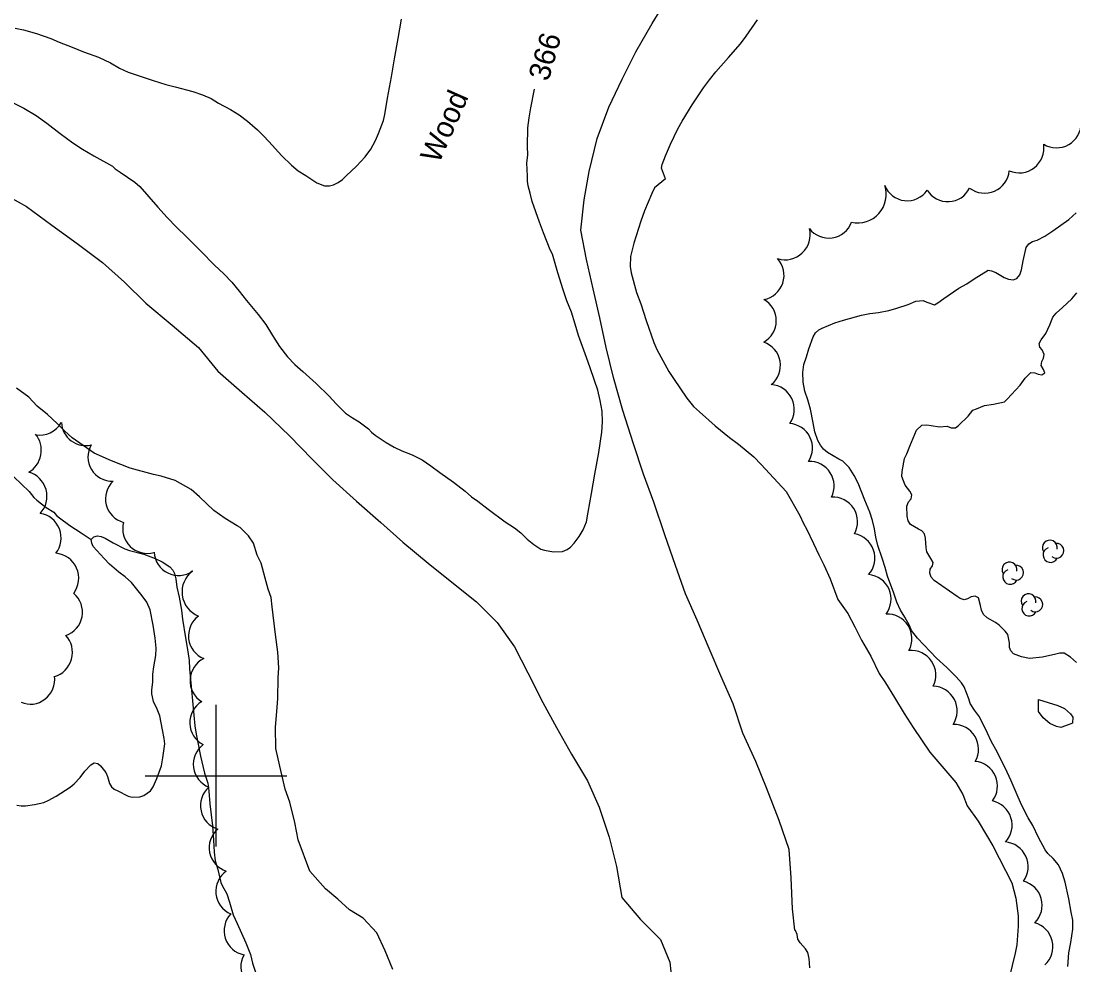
# Model space of a CAD drawing. Extents: x 287698 to 290158, y 5234163 to 5237182.
# Drawn here: x 288572.5 to 288721, y 5235573.3 to 5235706.5 of the extents above; entities that cross this region are included whole.
import ezdxf

# ---------------------------------------------------------------- set-up
doc = ezdxf.new("R2010")
doc.units = 0
for name, color, linetype in [('Niveau 2', 7, 'Continuous'), ('Niveau 4', 7, 'Continuous'), ('Niveau 44', 7, 'Continuous'), ('Niveau 61', 7, 'Continuous')]:
    doc.layers.add(name, color=color, linetype=linetype)

msp = doc.modelspace()

# ---------------------------------------------------------------- linework, layer by layer
at = {"layer": 'Niveau 2'}
for points in [[(288681.74, 5235578.21), (288681.41, 5235581.23), (288681.26, 5235585.59), (288680.94, 5235589.59), (288679.52, 5235593.66), (288677.73, 5235598.29), (288676.23, 5235602.03), (288674.42, 5235606.03), (288673.04, 5235610.13), (288671.32, 5235614.08), (288669.65, 5235617.95), (288667.95, 5235621.96), (288666.29, 5235625.7), (288664.88, 5235629.68), (288663.41, 5235634.01), (288661.82, 5235638.6), (288660.4, 5235642.55), (288658.95, 5235646.83), (288657.48, 5235651.54), (288656.13, 5235656.23), (288655.1, 5235660.45), (288654.22, 5235664.63), (288653.28, 5235668.75), (288652.31, 5235672.87), (288651.52, 5235677.02), (288652.02, 5235681.3), (288652.73, 5235685.31), (288653.85, 5235689.96), (288655.49, 5235694.37), (288657.38, 5235698.34), (288659.29, 5235702.19), (288661.62, 5235706.17), (288663.73, 5235709.65)], [(288571.63, 5235705.55), (288572.82, 5235705.29), (288574.67, 5235704.76), (288576.66, 5235704.06), (288577.84, 5235703.55), (288579.7, 5235702.86), (288581.31, 5235702.21), (288583.39, 5235701.44), (288585.12, 5235700.62), (288586.36, 5235699.9), (288587.62, 5235699.31), (288588.71, 5235698.95), (288591.11, 5235698.13), (288592.94, 5235697.56), (288594.23, 5235697.26), (288596.75, 5235696.61), (288598.09, 5235696.12), (288599.32, 5235695.58), (288600.37, 5235694.96), (288602.04, 5235694.05), (288603.26, 5235693.29), (288604.45, 5235692.39), (288605.86, 5235691.18), (288606.71, 5235690.35), (288607.46, 5235689.51), (288609.32, 5235687.53), (288610.69, 5235686.17), (288611.63, 5235685.41), (288612.71, 5235684.72), (288614.23, 5235683.68), (288615.33, 5235683.26), (288616.04, 5235683.26), (288616.6, 5235683.42), (288617.27, 5235683.73), (288617.88, 5235684.17), (288618.41, 5235684.69), (288619.86, 5235686.03), (288621.09, 5235687.36), (288621.87, 5235688.43), (288622.54, 5235689.66), (288622.97, 5235690.67), (288623.67, 5235692.5), (288623.84, 5235693.35), (288624.24, 5235695.64), (288624.77, 5235698.66), (288625.22, 5235701.2), (288625.72, 5235704.05), (288626.21, 5235706.82)], [(288663.51, 5235684.28), (288662.93, 5235685.78), (288663.04, 5235686.28), (288663.47, 5235687.49), (288664.19, 5235689.14), (288665.22, 5235691.3), (288665.84, 5235692.39), (288667.25, 5235694.72), (288668.84, 5235697.09), (288669.71, 5235698.25), (288670.62, 5235699.37), (288672.37, 5235701.37), (288674.07, 5235703.32), (288674.87, 5235704.39), (288676.5, 5235706.71)], [(288649.56, 5235667.05), (288649.03, 5235668.61), (288648.27, 5235670.98), (288647.51, 5235673.62), (288647.22, 5235674.25), (288646.24, 5235676.66), (288645.69, 5235678.16), (288644.65, 5235681.08), (288644.36, 5235682.24), (288644.08, 5235683.29), (288643.99, 5235683.91), (288644.01, 5235684.65), (288643.91, 5235686.51), (288644.03, 5235687.61), (288644.01, 5235688.89), (288644.04, 5235691.46), (288644.23, 5235692.88), (288644.48, 5235694.29), (288644.99, 5235696.92)], [(288570.05, 5235695.63), (288572.85, 5235694.25), (288574.63, 5235693.18), (288576.11, 5235692.1), (288578, 5235690.65), (288579.77, 5235689.34), (288581.16, 5235688.43), (288582.73, 5235687.52), (288585.37, 5235686.03), (288585.76, 5235685.66), (288586.47, 5235685.2), (288588.56, 5235683.79), (288589.26, 5235683.16), (288590.53, 5235681.74), (288591.78, 5235680.24), (288593.09, 5235678.8), (288594.41, 5235677.46), (288595.84, 5235676.09), (288597.85, 5235674.04), (288599.81, 5235672.05), (288601.09, 5235670.85), (288602.23, 5235669.69), (288603.3, 5235668.41), (288604.33, 5235667.09), (288605.96, 5235665.13), (288607.03, 5235663.69), (288607.99, 5235662.14), (288608.99, 5235660.61), (288610.08, 5235659.15), (288611.15, 5235658.04), (288612.28, 5235657.04), (288614.17, 5235655.35), (288616.01, 5235653.57), (288616.98, 5235652.52), (288618.29, 5235651.2), (288619.26, 5235650.53), (288620.23, 5235649.96), (288621.56, 5235648.96), (288621.96, 5235648.48), (288622.48, 5235648.09), (288624.02, 5235647.04), (288625.18, 5235646.37), (288626.24, 5235645.85), (288627.72, 5235645.28), (288629.11, 5235644.59), (288630.36, 5235643.73), (288631.63, 5235642.79), (288633.55, 5235641.46), (288635.2, 5235640.17), (288636.11, 5235639.37), (288637, 5235638.74), (288638.45, 5235637.61), (288640.85, 5235635.82), (288642.18, 5235634.99), (288643.05, 5235634.3), (288643.95, 5235633.4), (288644.9, 5235632.63), (288645.87, 5235631.98), (288646.42, 5235631.83), (288647.69, 5235631.6), (288648.93, 5235631.66), (288649.6, 5235631.95), (288650.05, 5235632.27), (288650.61, 5235632.83), (288651.29, 5235633.76), (288651.88, 5235634.69), (288652.31, 5235635.82), (288652.57, 5235637.2), (288653.04, 5235639.84), (288653.52, 5235642.58), (288654.06, 5235645.61), (288654.52, 5235648.51), (288654.61, 5235649.97), (288654.53, 5235651.48), (288654.28, 5235652.95), (288653.92, 5235654.43), (288653.48, 5235655.81), (288652.82, 5235657.74), (288652.13, 5235659.54), (288651.18, 5235662.16), (288650.74, 5235663.75), (288650.2, 5235665.44), (288649.56, 5235667.05)], [(288663.51, 5235684.28), (288661.93, 5235683), (288661.55, 5235682.2), (288660.5, 5235679.72), (288660.01, 5235678.29), (288659, 5235675.16), (288658.55, 5235673.3), (288658.49, 5235671.88), (288658.66, 5235670.98), (288659.37, 5235668.22), (288660.02, 5235666.61), (288660.78, 5235664.27), (288661.82, 5235661.14), (288662.28, 5235660.15), (288663.96, 5235657.04), (288664.62, 5235656.08), (288666.49, 5235653.32), (288667.42, 5235652.11), (288668.28, 5235651.35), (288670.49, 5235649.41), (288672.54, 5235647.73), (288673.82, 5235646.8), (288675.98, 5235645.04), (288677.01, 5235643.92), (288680.52, 5235640.11), (288682.48, 5235636.73), (288682.98, 5235635.6), (288683.38, 5235634.84), (288684.37, 5235632.77), (288685.16, 5235631.17), (288685.85, 5235629.76), (288686.75, 5235627.78), (288687.85, 5235624.86), (288689.22, 5235622.88), (288690.21, 5235621), (288691.19, 5235619.12), (288692.48, 5235616.86), (288693.66, 5235614.42), (288694.54, 5235613.1), (288695.82, 5235611.04), (288697.19, 5235608.78), (288698.47, 5235606.82), (288700.82, 5235603.34), (288704.51, 5235599.04), (288705.5, 5235597.35), (288706.1, 5235595.74), (288707.66, 5235593.59), (288708.84, 5235591.61), (288709.73, 5235590.11), (288712.39, 5235584.87), (288712.97, 5235582.73), (288713.3, 5235580.21), (288713.32, 5235578.75), (288713.09, 5235576.11), (288712.88, 5235574.95), (288712.04, 5235571.48)], [(288569.7, 5235682.35), (288573.22, 5235680.35), (288576.84, 5235677.7), (288580.4, 5235675.15), (288583.99, 5235672.46), (288587.06, 5235669.65), (288590.1, 5235666.73), (288593.81, 5235663.62), (288597.54, 5235660.46), (288600.27, 5235657.1), (288603.64, 5235654.13), (288606.9, 5235651.31), (288610.4, 5235647.96), (288613.58, 5235644.67), (288616.52, 5235641.75), (288619.86, 5235638.75), (288623.3, 5235635.75), (288626.39, 5235632.95), (288629.95, 5235630), (288633.29, 5235627.34), (288636.81, 5235624.56), (288639.72, 5235621.64), (288642.17, 5235618.19), (288644.03, 5235614.51), (288646.18, 5235610.33), (288648.09, 5235606.8), (288650.2, 5235603.06), (288652.49, 5235599.3), (288654.11, 5235595.58), (288655.54, 5235591.32), (288656.58, 5235587.21), (288657.34, 5235582.82), (288659.98, 5235579.72), (288662.79, 5235576.86), (288664.09, 5235573.67)], [(288603.01, 5235635.29), (288601.29, 5235636.31), (288599.69, 5235637.46), (288597.69, 5235639.38), (288596.49, 5235640.41), (288594.23, 5235641.67), (288592.26, 5235642.28), (288591.2, 5235642.52), (288587.89, 5235643.4), (288585.25, 5235644.46), (288582.81, 5235645.52), (288579.7, 5235647.68), (288578.63, 5235648.7), (288577.57, 5235649.72), (288576.23, 5235651.01), (288574.76, 5235652.16), (288573.56, 5235653.45), (288571.83, 5235654.73)], [(288624.99, 5235572.63), (288623.88, 5235575.3), (288622.7, 5235577.83), (288620.78, 5235579.88), (288618.85, 5235581.07), (288617.2, 5235582.56), (288615.47, 5235584.04), (288613.24, 5235586.54), (288611.59, 5235590.94), (288611.15, 5235593.42), (288610.45, 5235596.29), (288609.75, 5235598.11), (288609.04, 5235601.37), (288608.46, 5235603.85), (288608.41, 5235606.86), (288608.62, 5235609.08), (288608.72, 5235610.92), (288608.8, 5235613.81), (288608.9, 5235615.25), (288608.73, 5235617.46), (288608.41, 5235619.95), (288607.95, 5235623.86), (288607.79, 5235625.17), (288607.38, 5235626.34), (288606.95, 5235627.9), (288606.39, 5235629.99), (288605.84, 5235631.15), (288605.28, 5235632.85), (288604.61, 5235633.88), (288603.41, 5235635.04), (288603.01, 5235635.29)], [(288683.88, 5235572.9), (288683.8, 5235574.18), (288683.6, 5235575.05), (288683.28, 5235575.58), (288682.51, 5235576.42), (288682.19, 5235576.92), (288682.07, 5235577.6), (288681.86, 5235578.15), (288681.74, 5235578.21)], [(288664.09, 5235573.67), (288664.39, 5235571.06)]]:
    msp.add_lwpolyline(points, dxfattribs=at)
at = {"layer": 'Niveau 4'}
for points in [[(288719.01, 5235587.42), (288718.25, 5235588.32), (288717.47, 5235589), (288717.12, 5235589.52), (288716.19, 5235591.3), (288715.39, 5235592.98), (288714.72, 5235594.08), (288713.82, 5235595.82), (288713.3, 5235596.98), (288712.33, 5235599.3), (288711.76, 5235600.5), (288710.39, 5235603.26), (288709.48, 5235604.89), (288708.95, 5235606.02), (288707.84, 5235608.3), (288707.12, 5235609.25), (288706.54, 5235610.21), (288706.34, 5235610.85), (288705.69, 5235612.54), (288705.3, 5235613.13), (288704.53, 5235613.95), (288703.22, 5235615.27), (288701.77, 5235616.58), (288700.86, 5235617.54), (288699.09, 5235619.44), (288698.25, 5235620.52), (288697.94, 5235621.19), (288697.31, 5235622.38), (288696.67, 5235623.37), (288696.17, 5235624.51), (288695.72, 5235625.75), (288694.85, 5235628.19), (288694.53, 5235629.4), (288694.07, 5235630.7), (288693.49, 5235632.51), (288693.19, 5235633.7), (288693.02, 5235634.87), (288692.74, 5235636.04), (288692.34, 5235637.19), (288691.66, 5235638.91), (288690.71, 5235641.29), (288690.13, 5235642.37), (288689.45, 5235643.5), (288688.53, 5235644.41), (288687.95, 5235644.71), (288686.35, 5235645.63), (288685.82, 5235646.09), (288685.4, 5235646.65), (288685.02, 5235647.34), (288684.6, 5235648.55), (288684.33, 5235649.81), (288683.98, 5235651.73), (288683.61, 5235653.06), (288683.15, 5235654.31), (288682.94, 5235655.54), (288682.9, 5235656.91), (288683.01, 5235658.03), (288683.4, 5235659.11), (288683.74, 5235660.25), (288684.33, 5235661.96), (288684.67, 5235662.5), (288685.16, 5235662.93), (288685.62, 5235663.17), (288687.41, 5235663.93), (288688.65, 5235664.32), (288691.16, 5235665.02), (288692.34, 5235665.24), (288693.59, 5235665.4), (288695.02, 5235665.68), (288696.18, 5235665.98), (288697.78, 5235666.51), (288698.86, 5235666.99), (288699.9, 5235667.08), (288700.41, 5235666.86), (288701.48, 5235666.48), (288701.94, 5235666.75), (288702.81, 5235667.37), (288704.92, 5235668.83), (288706.06, 5235669.45), (288707.06, 5235670.15), (288709.05, 5235671.36), (288709.55, 5235671.27), (288710.13, 5235671.04), (288711.3, 5235670.35), (288711.94, 5235670.11), (288712.58, 5235670.01), (288713.12, 5235670.2), (288713.55, 5235670.73), (288713.78, 5235671.43), (288714, 5235672.69), (288714.41, 5235674.58), (288714.8, 5235675.08), (288715.32, 5235675.42), (288715.97, 5235675.59), (288717.08, 5235676.16), (288718.19, 5235676.91), (288720.45, 5235678.53), (288721.5, 5235679.48)], [(288711.84, 5235619.96), (288711.44, 5235620.42), (288710.63, 5235621.24), (288710.09, 5235621.61), (288708.92, 5235622.29), (288708.4, 5235622.78), (288708.1, 5235623.38), (288707.99, 5235624.01), (288707.71, 5235625.1), (288707.23, 5235625.33), (288706.64, 5235625.26), (288706.16, 5235624.96), (288705.67, 5235624.84), (288705.11, 5235625.03), (288704.68, 5235625.29), (288703.59, 5235626.06), (288701.42, 5235627.56), (288701.01, 5235628.02), (288700.82, 5235628.59), (288700.87, 5235629.18), (288701.18, 5235629.62), (288701.3, 5235630.12), (288700.95, 5235630.65), (288700.41, 5235631.63), (288700.3, 5235632.18), (288700.23, 5235633.52), (288700.06, 5235634.16), (288699.71, 5235634.55), (288699.2, 5235634.8), (288698.09, 5235635.45), (288697.78, 5235635.99), (288697.63, 5235636.63), (288697.57, 5235638.03), (288697.82, 5235638.65), (288698.2, 5235639.09), (288698.28, 5235639.63), (288698, 5235640.18), (288697.35, 5235641.03), (288696.87, 5235642.23), (288696.93, 5235642.95), (288697.25, 5235644.77), (288697.56, 5235645.42), (288697.99, 5235646.52), (288698.93, 5235648.78), (288699.7, 5235649.5), (288700.39, 5235649.54), (288700.99, 5235649.42), (288702.17, 5235649.27), (288703.29, 5235649.33), (288703.85, 5235649.11), (288704.46, 5235649.09), (288704.89, 5235649.46), (288706.22, 5235650.78), (288706.9, 5235651.61), (288707.4, 5235651.79), (288708.56, 5235652.28), (288709.8, 5235652.44), (288711.36, 5235652.78), (288711.75, 5235653.18), (288713.57, 5235655.15), (288714.29, 5235656.13), (288715.09, 5235656.9), (288715.64, 5235656.86), (288716.12, 5235656.67), (288716.65, 5235656.57), (288717.08, 5235656.87), (288716.89, 5235657.36), (288716.54, 5235657.9), (288716.63, 5235658.47), (288716.88, 5235658.95), (288716.96, 5235659.48), (288716.7, 5235660.1), (288716.35, 5235660.52), (288716.28, 5235661.03), (288716.54, 5235661.53), (288717.21, 5235662.43), (288717.75, 5235663.64), (288718.18, 5235664.73), (288718.67, 5235665.32), (288719.57, 5235666.11), (288720.88, 5235667.32), (288721.56, 5235668.19)], [(288571.44, 5235642.18), (288573.62, 5235640.14), (288574.29, 5235639.28), (288574.69, 5235638.89), (288576.01, 5235637.86), (288577.09, 5235637.21), (288577.47, 5235636.74), (288577.88, 5235636.4), (288579.36, 5235635.33), (288580.97, 5235634.31), (288582.37, 5235633.33)], [(288571.89, 5235595.85), (288572.5, 5235595.75), (288573.12, 5235595.77), (288574.35, 5235595.92), (288575.67, 5235596.23), (288576.3, 5235596.5), (288577.41, 5235597.11), (288579.43, 5235598.39), (288579.98, 5235598.87), (288580.8, 5235599.73), (288581.48, 5235600.65), (288582.33, 5235601.52), (288582.8, 5235601.8), (288583.3, 5235601.74), (288583.7, 5235601.39), (288584.43, 5235600.44), (288584.67, 5235599.88), (288584.98, 5235598.89), (288585.24, 5235598.43), (288585.63, 5235598.11), (288586.13, 5235597.89), (288587.62, 5235597.13), (288588.17, 5235596.99), (288589.26, 5235597.02), (288589.83, 5235597.2), (288590.77, 5235597.85), (288591.12, 5235598.44), (288591.64, 5235599.63), (288592.31, 5235601.4), (288592.5, 5235602.53), (288592.78, 5235604.52), (288592.7, 5235605.25), (288592.47, 5235606.49), (288592.05, 5235608.47), (288591.68, 5235609.42), (288591.2, 5235610.46), (288590.94, 5235611.58), (288590.93, 5235612.13), (288591.09, 5235613.21), (288591.1, 5235614.33), (288591.21, 5235615.38), (288591.49, 5235616.98), (288591.54, 5235618.01), (288591.43, 5235619.42), (288591.14, 5235621.24), (288590.73, 5235623.41), (288590.22, 5235624.5), (288589.58, 5235625.38), (288588.05, 5235627.28), (288587.18, 5235628.07), (288586.29, 5235628.73), (288584.98, 5235629.85), (288584.19, 5235630.67), (288582.68, 5235632.36), (288582.46, 5235632.83), (288582.37, 5235633.33)], [(288582.37, 5235633.33), (288582.73, 5235633.72), (288583.25, 5235633.85), (288583.77, 5235633.78), (288584.37, 5235633.54)], [(288584.37, 5235633.54), (288585.46, 5235632.9), (288587.13, 5235632.01), (288587.78, 5235631.81), (288589.83, 5235631.27), (288591.39, 5235630.67), (288592.41, 5235630.18), (288593.5, 5235629.51), (288593.9, 5235629.04), (288594.14, 5235628.55), (288594.32, 5235627.8), (288594.48, 5235626.6), (288594.82, 5235625.19), (288595.14, 5235623.39), (288595.29, 5235622.1), (288595.69, 5235619.47), (288596.05, 5235617.53), (288596.21, 5235616.27), (288596.28, 5235615.1), (288596.48, 5235612.62), (288596.71, 5235610.06), (288597.01, 5235607.04), (288597.2, 5235605.88), (288597.46, 5235604.71), (288597.81, 5235602.77), (288598.4, 5235600.37), (288598.83, 5235598.97), (288598.99, 5235597.8), (288599.15, 5235596.05), (288599.5, 5235592.94), (288599.67, 5235590.9), (288599.73, 5235589.21), (288599.91, 5235588), (288600.28, 5235586.75), (288600.67, 5235584.95), (288600.88, 5235584.49), (288601.53, 5235583.33), (288601.91, 5235582.15), (288602.42, 5235580.38), (288602.99, 5235579.13), (288604.21, 5235576.4), (288604.87, 5235574.75), (288605.17, 5235573.55), (288605.59, 5235572.29)], [(288721.54, 5235615.99), (288720.69, 5235616.75), (288719.78, 5235617.32), (288719.19, 5235617.3), (288718.61, 5235617.16), (288716.73, 5235616.75), (288714.88, 5235616.57), (288713.77, 5235616.77), (288712.63, 5235617.23), (288712.25, 5235617.62), (288712.08, 5235618.12), (288712.09, 5235618.78), (288711.84, 5235619.96)], [(288716.16, 5235610.74), (288718.88, 5235609.92), (288719.86, 5235609.47), (288720.71, 5235608.75), (288721.03, 5235608.28), (288720.97, 5235607.42), (288720.51, 5235607.21), (288719.32, 5235606.82), (288718.69, 5235606.96), (288717.75, 5235607.39), (288716.83, 5235608.18), (288716.19, 5235609.08), (288716.16, 5235610.74)], [(288720.3, 5235573.09), (288720.44, 5235575.01), (288720.72, 5235576.45), (288721.01, 5235578.32), (288721.03, 5235579.6), (288720.78, 5235580.72), (288720.43, 5235582.62), (288719.95, 5235584.99), (288719.57, 5235586.2), (288719.01, 5235587.42)]]:
    msp.add_lwpolyline(points, dxfattribs=at)
at = {"layer": 'Niveau 44'}
for centre, radius, start, end in [((288680.37, 5235676.38), 3.55, 252.4925, 14.1074), ((288676.23, 5235657.92), 3.49, 308.9911, 71.014), ((288678.2, 5235651.74), 3.48, 324.5202, 86.3336), ((288687.11, 5235635.84), 3.51, 331.2688, 93.1578), ((288689.59, 5235630.72), 3.48, 318.0606, 80.1195), ((288691.86, 5235624.93), 3.49, 322.6639, 84.6701), ((288599.57, 5235619.75), 3.46, 126.2053, 248.209), ((288694.82, 5235619.34), 3.48, 331.38, 93.0706), ((288599.82, 5235613.41), 3.48, 116.3423, 238.1872), ((288698.18, 5235614.2), 3.49, 333.5216, 95.0592), ((288701.2, 5235609.16), 3.48, 326.5947, 88.3876), ((288599.77, 5235607.49), 3.47, 120.9811, 242.9884), ((288704.23, 5235603.77), 3.47, 329.7889, 91.9447), ((288600.27, 5235601.62), 3.47, 126.5867, 248.5776), ((288602.51, 5235589.84), 3.47, 130.46, 252.345), ((288603.45, 5235583.69), 3.47, 125.0304, 246.7106), ((288604.63, 5235578.13), 3.48, 137.1179, 258.8591), ((288606.97, 5235573), 3.46, 150.4392, 272.5901)]:
    msp.add_arc(centre, radius, start, end, dxfattribs=at)
for centre, major_axis, ratio, start_param, end_param in [((288718.71, 5235692.12), (1.72, -3.03), 0.999995, 5.221483, 7.350297), ((288713.43, 5235688.61), (1.77, -3.03), 0.999771, 5.3485, 7.475104), ((288708.56, 5235685.75), (1.35, -3.25), 0.994394, 5.237507, 7.358025), ((288690.65, 5235682.04), (2.99, -2.68), 0.998956, 5.219771, 7.341538), ((288697.63, 5235684.62), (-0.15, -3.45), 0.992338, 5.140051, 7.292919), ((288703.36, 5235684.5), (0.11, -3.46), 0.994527, 5.242314, 7.358764), ((288686.54, 5235679.35), (-0.31, -3.44), 0.999929, 5.458876, 7.58296), ((288676.75, 5235670.64), (2.96, -1.83), 0.99993, 5.453729, 7.58461), ((288675.69, 5235664.23), (3.45, -0.12), 0.996943, 5.253336, 7.375154), ((288575.26, 5235651.43), (2.42, 2.43), 0.955864, 3.721264, 4.98798), ((288581.51, 5235650.03), (1.11, -3.25), 0.973051, 4.440815, 6.207491), ((288680.8, 5235646.27), (-1.44, 3.14), 0.999863, 3.702118, 5.786444), ((288572.18, 5235645.93), (0.13, 3.42), 0.922185, 3.632765, 5.481799), ((288585.39, 5235645.04), (-2.99, -1.78), 0.990966, 5.237061, 7.344118), ((288683.85, 5235640.92), (-1.95, 2.85), 0.999864, 3.634752, 5.72764), ((288572.9, 5235639.53), (-0.93, 3.3), 0.93922, 3.634628, 5.79015), ((288587.91, 5235639.11), (-3.42, -0.83), 0.985923, 5.243578, 7.34164), ((288574.86, 5235633.66), (-1.31, 3.17), 0.947587, 3.619718, 5.773933), ((288590.32, 5235634.88), (-2.41, -2.54), 0.991337, 5.211679, 7.322627), ((288717.76, 5235632.2), (-1.04, 0.14), 0.999986, 3.057798, 7.027673), ((288718.71, 5235631.76), (-1.04, 0.14), 0.999986, 1.044869, 4.931445), ((288576.99, 5235627.84), (3.31, 1.52), 0.983866, 5.21963, 7.317144), ((288594.72, 5235631.73), (-1.7, -3.01), 0.998998, 5.280908, 7.408036), ((288717.86, 5235631.16), (-1.04, 0.14), 0.999986, 5.184416, 9.123425), ((288712.07, 5235629.11), (-1.04, 0.14), 0.999986, 3.057798, 7.027673), ((288713.02, 5235628.67), (-1.04, 0.14), 0.999986, 1.044869, 4.931445), ((288598.88, 5235625.95), (2.25, -2.9), 0.999995, 3.117872, 5.244092), ((288712.17, 5235628.07), (-1.04, 0.14), 0.999986, 5.184416, 9.123425), ((288577.69, 5235623.08), (3.4, -0.63), 0.997801, 5.220712, 7.341987), ((288714.76, 5235624.63), (-1.04, 0.14), 0.999986, 3.057798, 7.027673), ((288715.71, 5235624.19), (-1.04, 0.14), 0.999986, 1.044869, 4.931445), ((288714.86, 5235623.59), (-1.04, 0.14), 0.999986, 5.184416, 9.123425), ((288576.56, 5235617.3), (0.91, 3.3), 0.917125, 3.633637, 5.791141), ((288573.93, 5235613.5), (1.52, 3.08), 0.951026, 3.163284, 5.31614), ((288706.9, 5235598.56), (-2.81, 2.05), 0.999995, 3.116857, 5.24535), ((288601.27, 5235595.78), (-3.38, -0.73), 0.999803, 5.216391, 7.345546), ((288708.96, 5235593.03), (3.32, 1.05), 0.999346, 5.219371, 7.344822), ((288711.22, 5235587.17), (3.17, 1.46), 0.999806, 5.217695, 7.345969), ((288713.21, 5235581.72), (3.35, 0.94), 0.999865, 5.218626, 7.342882), ((288714.7, 5235575.87), (3.41, 0.81), 0.999354, 5.222031, 7.347201)]:
    msp.add_ellipse(centre, major_axis=major_axis, ratio=ratio, start_param=start_param, end_param=end_param, dxfattribs=at)
at = {"layer": 'Niveau 61'}
for points in [[(288600, 5235610), (288600, 5235600), (288600, 5235590)], [(288590, 5235600), (288600, 5235600), (288610, 5235600)]]:
    msp.add_lwpolyline(points, dxfattribs=at)

# ---------------------------------------------------------------- texts
at = {"layer": 'Niveau 2'}
msp.add_text('366', height=3, rotation=73.7796, dxfattribs=at).set_placement((288646.94, 5235697.91))
at = {"layer": 'Niveau 44'}
msp.add_text('Wood', height=3, rotation=66.1212, dxfattribs=at).set_placement((288631.49, 5235686.29))

doc.saveas('drawing.dxf')
